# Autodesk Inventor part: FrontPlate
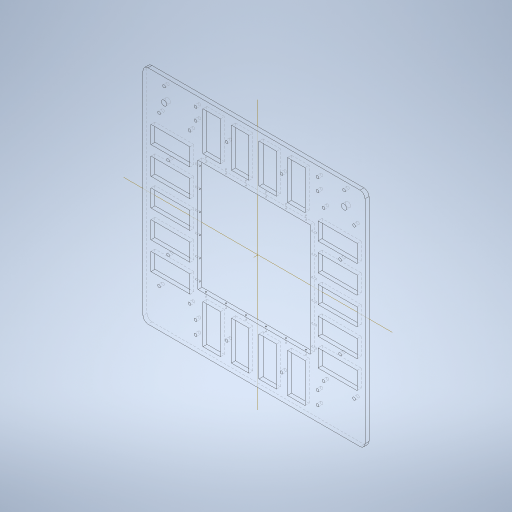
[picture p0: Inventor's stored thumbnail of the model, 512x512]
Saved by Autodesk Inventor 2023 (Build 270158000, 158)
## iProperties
Created: 2023-10
Part Number: FrontPlate
Material: Aluminum 7075
Document SubType Name: Modeling
Designer: tornqvih
Density: 2.81 g/cm^3
Appearance: Satin - Brushed Heavy
Mass: 2176.39 g
Surface Area: 2534.42 cm^2
Volume: 774.515 cm^3
Author: tornqvih
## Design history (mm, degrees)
sketch "Sketch1"
  geometry: L1 (-212, 222)-(212, 222); L2 (222, 212)-(222, -212); L3 (212, -222)-(-212, -222); L4 (-222, -212)-(-222, 212); L5 (-222, 222)-(222, -222); L6 (222, 222)-(-222, -222); L7 (0, -313.699)-(0, 313.699) reference; L8 (-313.699, 0)-(313.699, 0) reference; A1 r 10 centre (-212, 212) between (-212, 222) and (-222, 212); A2 r 10 centre (212, 212) between (222, 212) and (212, 222); A3 r 10 centre (-212, -212) between (-222, -212) and (-212, -222); A4 r 10 centre (212, -212) between (212, -222) and (222, -212)
  constraints: 12 end point, 8 point on circle, 8 point on line, 8 tangent, 4 centre point, 2 parallel, 1 horizontal, 1 perpendicular, 2 other
  dimensions: "d0" = 444 distance of L5.start L6.start; "d1" = 444 distance of L6.end L5.start; "d10" = 10 radius of A1 (derived); "d11" = 10 radius of A2 (derived); "d12" = 10 radius of A3 (derived); "d13" = 10 radius of A4 (derived)
extrude "Extrusion1" new body sketch "Sketch1" distance "d4" = 8; taper "d5" = 0 deg
sketch "Sketch2"
  geometry: L1 (-112, -112)-(112, -112); L2 (112, -112)-(112, 112); L3 (112, 112)-(-112, 112); L4 (-112, 112)-(-112, -112); L5 (-112, -112)-(112, 112); L6 (112, -112)-(-112, 112); L7 (-102, 206)-(-67, 206); L8 (-67, 206)-(-67, 128); L9 (-67, 128)-(-102, 128); L10 (-102, 128)-(-102, 206); L11 (212, 222)-(-212, 222) reference; L12 (-45, 206)-(-10, 206); L13 (-10, 206)-(-10, 128); L14 (-10, 128)-(-45, 128); L15 (-45, 128)-(-45, 206); L16 (0, -310.8)-(0, 310.8) reference; L17 (10, 206)-(45, 206); L18 (45, 206)-(45, 128); L19 (45, 128)-(10, 128); L20 (10, 128)-(10, 206); L21 (67, 206)-(102, 206); L22 (102, 206)-(102, 128); L23 (102, 128)-(67, 128); L24 (67, 128)-(67, 206); L25 (-102, -128)-(-67, -128); L26 (-67, -128)-(-67, -206); L27 (-67, -206)-(-102, -206); L28 (-102, -206)-(-102, -128); L29 (-45, -128)-(-10, -128); L30 (-10, -128)-(-10, -206); L31 (-10, -206)-(-45, -206); L32 (-45, -206)-(-45, -128); L33 (10, -128)-(45, -128); L34 (45, -128)-(45, -206); L35 (45, -206)-(10, -206); L36 (10, -206)-(10, -128); L37 (67, -128)-(102, -128); L38 (102, -128)-(102, -206); L39 (102, -206)-(67, -206); L40 (67, -206)-(67, -128); L41 (-310.8, 0)-(310.8, 0) reference; L42 (-206, 127)-(-128, 127); L43 (-128, 127)-(-128, 92); L44 (-128, 92)-(-206, 92); L45 (-206, 92)-(-206, 127); L46 (-206, 72)-(-128, 72); L47 (-128, 72)-(-128, 37); L48 (-128, 37)-(-206, 37); L49 (-206, 37)-(-206, 72); L50 (-206, 17)-(-128, 17); L51 (-128, 17)-(-128, -18); L52 (-128, -18)-(-206, -18); L53 (-206, -18)-(-206, 17); L54 (-206, -38)-(-128, -38); L55 (-128, -38)-(-128, -73); L56 (-128, -73)-(-206, -73); L57 (-206, -73)-(-206, -38); L58 (-206, -93)-(-128, -93); L59 (-128, -93)-(-128, -128); L60 (-128, -128)-(-206, -128); L61 (-206, -128)-(-206, -93); L62 (-222, 212)-(-222, -212) reference; L63 (128, 127)-(206, 127); L64 (206, 127)-(206, 92)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; 1 further point
  constraints: 156 end point, 44 symmetric about line, 18 point on line, 16 parallel, 8 horizontal, 8 perpendicular, 8 vertical alignment, 2 horizontal alignment, 2 midpoint
  dimensions: "d6" = 224 distance of L2.end L3.end; "d7" = 224 distance of L3.end L1.start; "d79" = 10 distance between parallel lines of L4 L10; "d80" = 35 distance between parallel lines of L8 L10; "d81" = 16 distance between parallel lines of L11 L7; "d82" = 16 distance between parallel lines of L3 L9; "d83" = 35 distance between parallel lines of L13 L15; "d84" = 10 distance between parallel lines of L16 L13; "d85" = 16 distance between parallel lines of L4 L43; "d86" = 16 distance between parallel lines of L62 L45; "d87" = 35 distance between parallel lines of L44 L42; "d88" = 15 distance between parallel lines of L3 L42; "d89" = 35 distance between parallel lines of L48 L46; "d90" = 35 distance between parallel lines of L52 L50; "d91" = 35 distance between parallel lines of L56 L54; "d92" = 35 distance between parallel lines of L60 L58; "d93" = 20 distance between parallel lines of L46 L44; "d94" = 20 distance between parallel lines of L50 L48; "d95" = 20 distance between parallel lines of L54 L52; "d96" = 20 distance between parallel lines of L58 L56
extrude "Extrusion2" cut sketch "Sketch2" distance "d8" = 8; taper "d9" = 0 deg
sketch "Sketch3"
  geometry: L1 (-222, 212)-(-222, -212) reference; L2 (212, 222)-(-212, 222) reference; L3 (0, -310.8)-(0, 310.8) reference; L4 (-310.8, 0)-(310.8, 0) reference; L5 (-112, -112)-(-112, 112) reference; L6 (-212, -222)-(212, -222) reference; L7 (112, 112)-(112, -112) reference; L8 (222, -212)-(222, 212) reference; L9 (112, -112)-(-112, -112) reference; 30 further points
  constraints: 10 horizontal alignment, 10 vertical alignment, 7 symmetric about line, 3 coincident
  dimensions: "d23" = 67 distance from line of L2 point (-190, 155); "d24" = 20 distance from line of L2 point (-117, 202); "d26" = 17 distance from line of L5 point (-129, 155); "d64" = 24 distance of point (-117, 178) point (-117, 202); "d66" = 29 distance from line of L6 point (-117, -193); "d67" = 26 distance of point (-117, -167) point (-117, -193); "d69" = 15 distance from line of L7 point (127, 178); "d70" = 22 distance from line of L8 point (200, 155); "d71" = 61 distance of point (200, 155) point (139, 155); "d72" = 5 horizontal distance of L5.end point (-117, 202); "d73" = 61 distance of point (-129, 155) point (-190, 155); "d74" = 33 distance from line of L9 point (-190, -145); "d75" = 55 distance from line of L3 point (-55, 172); "d76" = 50 distance from line of L2 point (-55, 172); "d77" = 82 distance from line of L4 point (-172, 82); "d78" = 50 distance from line of L1 point (-172, 82); "d106" = 180 distance from line of L3 point (-180, 206); "d107" = 16 distance from line of L2 point (-180, 206)
hole "Hole1" sketch "Sketch3" diameter "d14" = 5.5; stored, may be unused: countersink angle "d18" = 90 deg, drill point angle "d20" = 118 deg; dims "d15" = 6, "d16" = 4, "d17" = 2, "d19" = 8
sketch "Sketch4"
  geometry: L1 (112, 9.6)-(112, -1.6) reference; L2 (324, 0)-(-100, 0) reference; 7 further points
  constraints: 3 symmetric about line, 2 horizontal alignment
  dimensions: "d28" = 4 distance from line of L2 point (12, 4); "d29" = 20 distance from line of L1 point (92, 4); "d30" = 60 distance from line of L1 point (52, 4); "d31" = 100 distance from line of L1 point (12, 4)
hole "Hole2" sketch "Sketch4" at (12, 4), (52, 4), (92, 4), (132, 4), (172, 4), (212, 4) diameter "d32" = 2.459; stored, may be unused: countersink angle "d36" = 90 deg, drill point angle "d38" = 118 deg; dims "d33" = 6, "d34" = 4, "d35" = 2, "d37" = 8.8
sketch "Sketch5"
  geometry: L1 (9.6, 112)-(-1.6, 112) reference; L2 (8, -100)-(8, 324) reference; 7 further points
  constraints: 3 symmetric about line, 2 vertical alignment
  dimensions: "d39" = 4 distance from line of L2 point (4, 212); "d40" = 20 distance from line of L1 point (4, 132); "d41" = 60 distance from line of L1 point (4, 172); "d42" = 100 distance from line of L1 point (4, 212)
hole "Hole3" sketch "Sketch5" at (4, 212), (4, 172), (4, 132), (4, 92), (4, 52), (4, 12) diameter "d43" = 2.459; stored, may be unused: countersink angle "d47" = 90 deg, drill point angle "d49" = 118 deg; dims "d44" = 6, "d45" = 4, "d46" = 2, "d48" = 8.8
sketch "Sketch6"
  geometry: C1 r 1.23 at (12, -4) reference; C2 r 1.23 at (52, -4) reference; C3 r 1.23 at (92, -4) reference; C4 r 1.23 at (132, -4) reference; C5 r 1.23 at (172, -4) reference; C6 r 1.23 at (212, -4) reference; 7 further points
  constraints: 6 coincident
hole "Hole4" sketch "Sketch6" at (12, -4), (52, -4), (92, -4), (132, -4), (172, -4), (212, -4) diameter "d50" = 2.459; stored, may be unused: countersink angle "d54" = 90 deg, drill point angle "d56" = 118 deg; dims "d51" = 6, "d52" = 4, "d53" = 2, "d55" = 8.8
sketch "Sketch7"
  geometry: C1 r 1.23 at (-4, 212) reference; C2 r 1.23 at (-4, 172) reference; C3 r 1.23 at (-4, 132) reference; C4 r 1.23 at (-4, 92) reference; C5 r 1.23 at (-4, 52) reference; C6 r 1.23 at (-4, 12) reference; 7 further points
  constraints: 6 coincident
hole "Hole5" sketch "Sketch7" at (-4, 212), (-4, 172), (-4, 132), (-4, 92), (-4, 52), (-4, 12) diameter "d57" = 2.459; stored, may be unused: countersink angle "d61" = 90 deg, drill point angle "d63" = 118 deg; dims "d58" = 6, "d59" = 4, "d60" = 2, "d62" = 8.8
sketch "Sketch8"
  geometry: L1 (212, 222)-(-212, 222) reference; L2 (0, -310.8)-(0, 310.8) reference; 3 further points
  constraints: 1 symmetric about line
  dimensions: "d97" = 45 distance from line of L1 point (-180, 177); "d98" = 180 distance from line of L2 point (-180, 177)
hole "Hole6" sketch "Sketch8" at (-180, 177), (180, 177) diameter "d99" = 10.5; stored, may be unused: countersink angle "d103" = 90 deg, drill point angle "d105" = 118 deg; dims "d100" = 6, "d101" = 4, "d102" = 2, "d104" = 8
node "FrontPlate"
